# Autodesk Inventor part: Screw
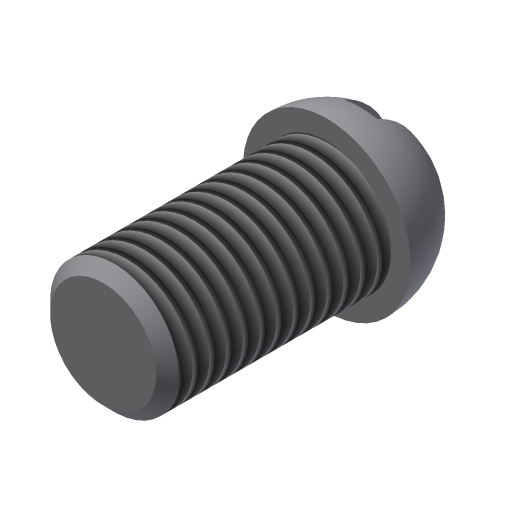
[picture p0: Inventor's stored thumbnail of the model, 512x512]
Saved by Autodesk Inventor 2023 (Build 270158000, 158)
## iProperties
Created: 2002-01
Part Number: Screw
Document SubType Name: Modeling
Designer: ***
Density: 1 g/cm^3
Material: Generic
Appearance: Default
Control State: 0
Master: False
Checked Out: False
Shininess: 77.0
Length Units: 11269
Angle Units: 11279
Time Units: 11290
Mass Units: 11283
Length Display Precision: 3
Angle Display Precision: 2
Density: 0.0
Volumn: 0.0
Area: 0.0
PropertySet Name: Model Information
Author: ***
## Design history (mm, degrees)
sketch "Sketch1"
  geometry: L1 (-0.061, 13.328)-(-0.061, -1.672); L2 (-0.061, -1.672)-(14.939, -1.672); A1 r 15 centre (-0.061, -1.672) between (14.939, -1.672) and (-0.061, 13.328)
  constraints: 4 end point, 2 point on circle, 1 centre point
  dimensions: "d0" = 15 radius of A1
revolve "Revolution1" sketch "Sketch1" stored, may be unused: angle "d3" = 90 deg
workplane "Work Plane2"
sketch "Sketch3"
  geometry: L1 (-3, 26)-(3, 26); L2 (3, 26)-(3, 6); L3 (3, 6)-(-3, 6); L4 (-3, 6)-(-3, 26); L5 (-15, 0)-(15, 0) reference
  constraints: 8 end point, 2 parallel, 1 horizontal, 1 perpendicular
  dimensions: "d11" = 6 distance of L1.start L1.end; "d12" = 20 distance of L3.end L1.start; "d13" = 6 distance between parallel lines of L5 L3; "d14" = 12 distance from line of L4 L5.start
extrude "Extrusion2" cut sketch "Sketch3" extent not by distance; stored distance "d15" = 10; taper "d16" = 0 deg
sketch "Sketch4"
  geometry: C1 r 11.5 at (0, 0); C2 r 15 at (0, 0) reference
  constraints: 1 centre point, 1 concentric
  dimensions: "d17" = 23 diameter of C1
extrude "Extrusion3" join sketch "Sketch4" distance "d18" = 40; taper "d19" = 0 deg
chamfer "Chamfer1" distance "d20" = 2; stored, may be unused: second distance "d21" = 2, angle "d24" = 45 deg
thread "Thread1" dims "d22" = 10, "d23" = 0
body "Solid1"
